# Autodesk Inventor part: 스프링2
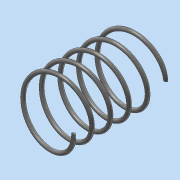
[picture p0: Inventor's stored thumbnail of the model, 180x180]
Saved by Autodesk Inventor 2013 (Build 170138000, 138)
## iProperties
Created: 2015-11
Part Number: 스프링2
Material: 강철, 탄소
Document SubType Name: Modeling
Designer: dgall
Density: 7.87 g/cm^3
Mass: 1.48738 g
Surface Area: 7.67156 cm^2
Volume: 0.188993 cm^3
Author: dgall
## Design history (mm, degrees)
sketch "스케치1"
  geometry: L1 (0, 0)-(8, 0); L2 (0, 0)-(0, 26); L3 (0, 26)-(8, 26); C1 r 0.5 at (8, 0)
  constraints: 6 end point, 2 perpendicular, 1 centre point, 1 coincident, 1 horizontal, 1 vertical alignment
  dimensions: "d0" = 16 diameter of L1.end L2; "d2" = 26 distance of L1.start L2.end (derived); "d3" = 1 diameter of C1
feature "코일1" sketch "스케치1" pitch "d4" = 10; turns "d6" = 5; dims "d5" = 26 (= d2), "d7" = 0, angle "d8" = 90 deg, angle "d9" = 90 deg, "d10" = 0, "d11" = 0
node "작업 평면1"
feature "분할1"
feature "분할2"
node "솔리드1"
other parameters: "d12" = 25
